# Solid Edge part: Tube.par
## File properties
Username: m_hel
Author: m_hel
Template: Iso Metric Part.par
Last saved by: m_hel
Revision: 4
Application: Solid Edge
Accuracy: 0,990
Material: Rubber
Face Style: Black (dull)
Fill Style: Normal
Virtual Style: Normal
Grouping: Uncategorized
LibraryName: Custom Materials
Coef. of Thermal Exp: 0.0
Thermal Conductivity: 0.0
Specific Heat: 0.0
Modulus of Elasticity: 0.0
Poisson's Ratio: 0.0
Yield Stress: 0.0
Ultimate Stress: 0.0
Elongation: 0.0
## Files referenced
..\..\Redfisher18.asm
G:\OneDriveTemp\OneDrive\Dokumendid\TLÜ tööd\3D Modelleerimine\3d modelling\veesõiduk\Boxes\Back well.par
G:\OneDriveTemp\OneDrive\Dokumendid\TLÜ tööd\3D Modelleerimine\3d modelling\veesõiduk\Engine\Enginev2.par
iduk\Boxes\Back well.par
iduk\Engine\Enginev2.par
iduk\Redfisher18.asm
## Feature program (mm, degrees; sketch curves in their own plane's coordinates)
swept protrusion "SweptProtrusion_1"
sketch for "ExtrudedProtrusion_1" plane through (0, 0, 0) normal (0, -1, 0) x-axis (1, 0, 0)
  circle centre (0, 0) radius 25
extrude "ExtrudedProtrusion_1" add finite 50 along +normal
sketch for "unnamed Protrusion 1" plane through (147.5363, 308.192, -376.5535) normal (0.984808, 0.173648, 0) x-axis (0, 0, 1)
  circle centre (0, 0) radius 25
extrude "unnamed Protrusion 1" add to key point along +normal
swept cutout "SweptCutout_6"
Other named dimensions: "KeypointCurve_1": EndDerivMagnitude = 1444.4494 mm | "SweptSurface_1": Twist_Turns = 1; Turns_Length = 12 mm; Scale_Start = 1; Scale_End = 1
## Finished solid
Body 1: sheet body, 1 face, 4 edges, 4 vertices.
  Faces by surface: spline 1
  Edges by curve: line 2, spline 2
Body 2: solid body, 8 faces, 14 edges, 8 vertices.
  Faces by surface: plane 4, cylinder 2, spline 2
  Edges by curve: circle 6, intersection 6, ellipse 2
Body 3: sheet body, 1 face, 5 edges, 4 vertices.
  Faces by surface: plane 1
  Edges by curve: circle 5
Body 4: sheet body, 1 face, 5 edges, 4 vertices.
  Faces by surface: plane 1
  Edges by curve: circle 5
Bounding box of the edges (mm; curved faces can reach further): 446.624 x 395.122 x 483.306, from (-225.8102, -50, -449.5564) to (220.8141, 345.1223, 33.75).
Cylindrical faces by radius (mm): R25 x2
Planar faces by outward normal: -y 1, oblique 3
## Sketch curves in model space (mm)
line (0, 0, 0) -> (25, 0, 0)
circle centre (0, 0, 0) radius 25
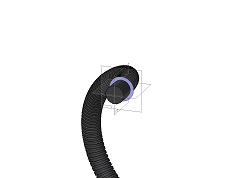
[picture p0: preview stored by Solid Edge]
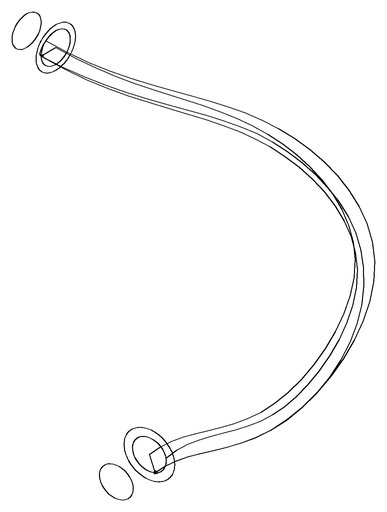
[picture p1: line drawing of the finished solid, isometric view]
